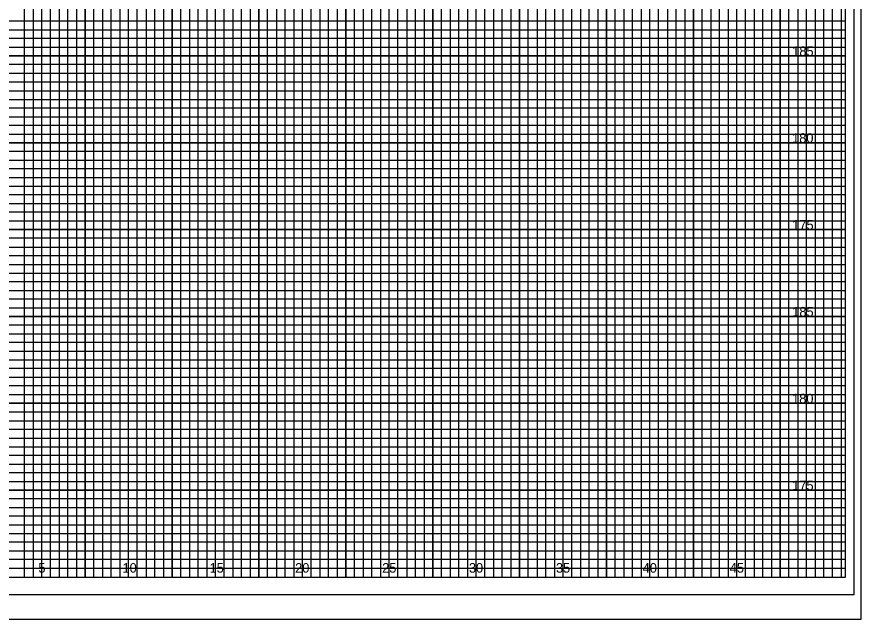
# Model space of a CAD drawing. Extents: x -4 to 103, y -2 to 280.
# Drawn here: x 54.82 to 103.4, y -2.43 to 32.25 of the extents above; entities that cross this region are included whole.
import ezdxf

# ---------------------------------------------------------------- set-up
doc = ezdxf.new("R2010")
doc.units = 0
for name, color, linetype in [('Exist XS Center Line Elevation Label', 7, 'Continuous'), ('Old_Level_63', 7, 'Continuous'), ('Prop XS Dump Level', 7, 'Continuous'), ('Prop XS Pvmt Edge Slope', 7, 'Continuous'), ('Prop XS SE Text', 7, 'Continuous'), ('Prop XS Subgrade Earthwork', 7, 'Continuous'), ('Sheet Cutting Line CELL', 7, 'Continuous'), ('Sheet Plot Border Inside CELL', 7, 'Continuous'), ('Sheet Plot Border Outside CELL', 7, 'Continuous')]:
    doc.layers.add(name, color=color, linetype=linetype)

msp = doc.modelspace()

# ---------------------------------------------------------------- linework, layer by layer
at = {"layer": 'Exist XS Center Line Elevation Label'}
for points in [[(56.25, 0), (56.25, 65)], [(58.75, 65), (58.75, 0), (61.25, 0), (61.25, 65)], [(63.75, 65), (63.75, 0), (66.25, 0), (66.25, 65)], [(68.75, 65), (68.75, 0), (71.25, 0), (71.25, 65)], [(73.75, 65), (73.75, 0), (76.25, 0), (76.25, 62)], [(88.75, 62), (88.75, 0), (91.25, 0), (91.25, 63.425)], [(93.75, 63.425), (93.75, 0), (96.25, 0), (96.25, 63.425)], [(98.75, 63.425), (98.75, 0), (101.25, 0), (101.25, 63.425)], [(78.75, 62), (78.75, 0), (81.25, 0), (81.25, 62)], [(83.75, 62), (83.75, 0), (86.25, 0), (86.25, 62)], [(0, 27.5), (102.5, 27.5), (102.5, 30), (0, 30)], [(0, 22.5), (102.5, 22.5), (102.5, 25), (0, 25)], [(0, 17.5), (102.5, 17.5), (102.5, 20), (0, 20)], [(0, 12.5), (102.5, 12.5), (102.5, 15), (0, 15)], [(0, 7.5), (102.5, 7.5), (102.5, 10), (0, 10)], [(0, 2.5), (102.5, 2.5), (102.5, 5), (0, 5)]]:
    msp.add_lwpolyline(points, dxfattribs=at)
at = {"layer": 'Old_Level_63'}
msp.add_lwpolyline([(102.5, 65), (0, 65), (0, 0), (102.5, 0)], close=True, dxfattribs=at)
at = {"layer": 'Prop XS Dump Level'}
for p, q in [((56.25, 0), (56.25, 65)), ((58.75, 0), (58.75, 65)), ((61.25, 0), (61.25, 65)), ((63.75, 0), (63.75, 65)), ((66.25, 0), (66.25, 65)), ((68.75, 0), (68.75, 65)), ((71.25, 0), (71.25, 65)), ((73.75, 0), (73.75, 65)), ((91.25, 0), (91.25, 63.425)), ((93.75, 0), (93.75, 63.425)), ((96.25, 0), (96.25, 63.425)), ((98.75, 0), (98.75, 63.425)), ((101.25, 0), (101.25, 63.425)), ((76.25, 0), (76.25, 62)), ((78.75, 0), (78.75, 62)), ((81.25, 0), (81.25, 62)), ((83.75, 0), (83.75, 62)), ((86.25, 0), (86.25, 62)), ((88.75, 0), (88.75, 62)), ((0, 30), (102.5, 30)), ((0, 27.5), (102.5, 27.5)), ((0, 25), (102.5, 25)), ((0, 22.5), (102.5, 22.5)), ((0, 20), (102.5, 20)), ((0, 17.5), (102.5, 17.5)), ((0, 15), (102.5, 15)), ((0, 12.5), (102.5, 12.5)), ((0, 10), (102.5, 10)), ((0, 7.5), (102.5, 7.5)), ((0, 5), (102.5, 5)), ((0, 2.5), (102.5, 2.5))]:
    msp.add_line(p, q, dxfattribs=at)
at = {"layer": 'Prop XS SE Text'}
for points in [[(54.75, 0), (55.25, 0), (55.25, 65)], [(55.75, 65), (55.75, 0), (56.75, 0), (56.75, 65)], [(57.25, 65), (57.25, 0), (57.75, 0), (57.75, 65)], [(58.25, 65), (58.25, 0), (59.25, 0), (59.25, 65)], [(59.75, 65), (59.75, 0), (60.25, 0), (60.25, 65)], [(60.75, 65), (60.75, 0), (61.75, 0), (61.75, 65)], [(62.25, 65), (62.25, 0), (62.75, 0), (62.75, 65)], [(63.25, 65), (63.25, 0), (64.25, 0), (64.25, 65)], [(64.75, 65), (64.75, 0), (65.25, 0), (65.25, 65)], [(65.75, 65), (65.75, 0), (66.75, 0), (66.75, 65)], [(67.25, 65), (67.25, 0), (67.75, 0), (67.75, 65)], [(68.25, 65), (68.25, 0), (69.25, 0), (69.25, 65)], [(69.75, 65), (69.75, 0), (70.25, 0), (70.25, 65)], [(70.75, 65), (70.75, 0), (71.75, 0), (71.75, 65)], [(72.25, 65), (72.25, 0), (72.75, 0), (72.75, 65)], [(73.25, 65), (73.25, 0), (74.25, 0), (74.25, 62)], [(89.75, 62), (89.75, 0), (90.25, 0), (90.25, 63.425)], [(90.75, 63.425), (90.75, 0), (91.75, 0), (91.75, 63.425)], [(92.25, 63.425), (92.25, 0), (92.75, 0), (92.75, 63.425)], [(93.25, 63.425), (93.25, 0), (94.25, 0), (94.25, 63.425)], [(94.75, 63.425), (94.75, 0), (95.25, 0), (95.25, 63.425)], [(95.75, 63.425), (95.75, 0), (96.75, 0), (96.75, 63.425)], [(97.25, 63.425), (97.25, 0), (97.75, 0), (97.75, 63.425)], [(98.25, 63.425), (98.25, 0), (99.25, 0), (99.25, 63.425)], [(99.75, 63.425), (99.75, 0), (100.25, 0), (100.25, 63.425)], [(100.25, 63.425), (100.75, 63.425), (100.75, 0), (101.75, 0), (101.75, 63.425), (102.25, 63.425), (102.25, 0)], [(74.75, 62), (74.75, 0), (75.25, 0), (75.25, 62)], [(75.75, 62), (75.75, 0), (76.75, 0), (76.75, 62)], [(77.25, 62), (77.25, 0), (77.75, 0), (77.75, 62)], [(78.25, 62), (78.25, 0), (79.25, 0), (79.25, 62)], [(79.75, 62), (79.75, 0), (80.25, 0), (80.25, 62)], [(80.75, 62), (80.75, 0), (81.75, 0), (81.75, 62)], [(82.25, 62), (82.25, 0), (82.75, 0), (82.75, 62)], [(83.25, 62), (83.25, 0), (84.25, 0), (84.25, 62)], [(84.75, 62), (84.75, 0), (85.25, 0), (85.25, 62)], [(85.75, 62), (85.75, 0), (86.75, 0), (86.75, 62)], [(87.25, 62), (87.25, 0), (87.75, 0), (87.75, 62)], [(88.25, 62), (88.25, 0), (89.25, 0), (89.25, 62)], [(0, 31.5), (102.5, 31.5), (102.5, 32), (0, 32)], [(0, 30.5), (102.5, 30.5), (102.5, 31), (0, 31)], [(0, 29), (102.5, 29), (102.5, 29.5), (0, 29.5)], [(0, 28), (102.5, 28), (102.5, 28.5), (0, 28.5)], [(0, 26.5), (102.5, 26.5), (102.5, 27), (0, 27)], [(0, 25.5), (102.5, 25.5), (102.5, 26), (0, 26)], [(0, 24), (102.5, 24), (102.5, 24.5), (0, 24.5)], [(0, 23), (102.5, 23), (102.5, 23.5), (0, 23.5)], [(0, 21.5), (102.5, 21.5), (102.5, 22), (0, 22)], [(0, 20.5), (102.5, 20.5), (102.5, 21), (0, 21)], [(0, 19), (102.5, 19), (102.5, 19.5), (0, 19.5)], [(0, 18), (102.5, 18), (102.5, 18.5), (0, 18.5)], [(0, 16.5), (102.5, 16.5), (102.5, 17), (0, 17)], [(0, 15.5), (102.5, 15.5), (102.5, 16), (0, 16)], [(0, 14), (102.5, 14), (102.5, 14.5), (0, 14.5)], [(0, 13), (102.5, 13), (102.5, 13.5), (0, 13.5)], [(0, 11.5), (102.5, 11.5), (102.5, 12), (0, 12)], [(0, 10.5), (102.5, 10.5), (102.5, 11), (0, 11)], [(0, 9), (102.5, 9), (102.5, 9.5), (0, 9.5)], [(0, 8), (102.5, 8), (102.5, 8.5), (0, 8.5)], [(0, 6.5), (102.5, 6.5), (102.5, 7), (0, 7)], [(0, 5.5), (102.5, 5.5), (102.5, 6), (0, 6)], [(0, 4), (102.5, 4), (102.5, 4.5), (0, 4.5)], [(0, 3), (102.5, 3), (102.5, 3.5), (0, 3.5)], [(0, 1.5), (102.5, 1.5), (102.5, 2), (0, 2)], [(0, 0.5), (102.5, 0.5), (102.5, 1), (0, 1)]]:
    msp.add_lwpolyline(points, dxfattribs=at)
at = {"layer": 'Sheet Cutting Line CELL'}
msp.add_line((-3.5, -2.425), (103.4, -2.425), dxfattribs=at)
at = {"layer": 'Sheet Plot Border Inside CELL'}
msp.add_lwpolyline([(103, 66), (-2.8, 66), (-2.8, -1), (103, -1)], close=True, dxfattribs=at)
at = {"layer": 'Sheet Plot Border Outside CELL'}
msp.add_lwpolyline([(103.4, 67.4), (-3.5, 67.4), (-3.5, -2.425), (103.4, -2.425)], close=True, dxfattribs=at)

# ---------------------------------------------------------------- texts
at = {"layer": 'Prop XS Pvmt Edge Slope'}
for s, p in [('5', (56.057, 0.25)), ('10', (60.897, 0.25)), ('15', (65.906, 0.25)), ('20', (70.831, 0.25)), ('25', (75.84, 0.25)), ('30', (80.831, 0.25)), ('35', (85.84, 0.25)), ('40', (90.831, 0.25)), ('45', (95.84, 0.25))]:
    msp.add_text(s, height=0.55, dxfattribs=at).set_placement(p)
at = {"layer": 'Prop XS Subgrade Earthwork'}
for s, p in [('185', (99.438, 30)), ('180', (99.43, 25)), ('175', (99.438, 20)), ('185', (99.438, 15)), ('180', (99.43, 10)), ('175', (99.438, 5))]:
    msp.add_text(s, height=0.55, dxfattribs=at).set_placement(p)

doc.saveas('drawing.dxf')
